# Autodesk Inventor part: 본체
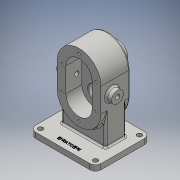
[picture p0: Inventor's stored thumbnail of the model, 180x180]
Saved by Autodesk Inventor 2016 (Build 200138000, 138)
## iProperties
Created: 2020-09
Part Number: 본체
Material: 일반
Document SubType Name: Modeling
Designer: Windows7
Density: 1 g/cm^3
Appearance: 기본값
Author: Windows7
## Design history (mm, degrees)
sketch "스케치1"
  geometry: L1 (60, -50)-(-60, -50); L2 (-60, -50)-(-60, 50); L3 (-60, 50)-(60, 50); L4 (60, 50)-(60, -50); L5 (60, -50)-(-60, 50); L6 (-60, -50)-(60, 50); 1 further point
  constraints: 12 end point, 2 midpoint, 2 parallel, 1 horizontal, 1 perpendicular
  dimensions: "d0" = 120 distance of L2.end L3.end; "d1" = 100 distance of L3.end L1.start
extrude "돌출1" new body sketch "스케치1" distance "d2" = 10; taper "d3" = 0 deg
sketch "스케치6"
  geometry: 1 further point
node "작업 평면3"
sketch "스케치7"
  geometry: L1 (120, 0)-(0, 0) reference; L2 (60, 0)-(60, -90); L3 (20, -68)-(100, -68); L4 (100, -68)-(100, -112); L5 (100, -112)-(20, -112); L6 (20, -112)-(20, -68); L7 (20, -68)-(100, -112); L8 (100, -68)-(20, -112); A1 r 40 centre (60, -112) between (20, -112) and (100, -112); A2 r 40 centre (60, -68) between (100, -68) and (20, -68)
  constraints: 14 end point, 4 point on circle, 2 centre point, 2 midpoint, 2 parallel, 1 horizontal, 1 perpendicular, 1 vertical
  dimensions: "d22" = 90 distance of L2.start L2.end; "d23" = 44 distance of L5.end L3.start; "d24" = 80 distance between parallel lines of L6 L4; "d25" = 40 radius of A1; "d26" = 40 radius of A2
extrude "돌출3" join sketch "스케치7" distance "d27" = 53; taper "d28" = 0 deg
sketch "스케치8"
  geometry: 1 further point
sketch "스케치9"
  geometry: L1 (20, 112)-(20, 68) reference; L2 (100, 68)-(100, 112) reference; L3 (36, 112)-(36, 68); L4 (84, 112)-(84, 68); L5 (60, 0)-(60, 171.433); A1 r 40 centre (60, 112) between (100, 112) and (20, 112) reference; A2 r 40 centre (60, 68) between (20, 68) and (100, 68) reference; A3 r 24 centre (60, 112) between (84, 112) and (36, 112); A4 r 24 centre (60, 68) between (36.002, 68.312) and (84, 68)
  constraints: 6 end point, 5 point on circle, 2 centre point, 2 vertical, 1 tangent, 1 other
  dimensions: "d29" = 24 radius of A3; "d30" = 24 radius of A4
extrude "돌출4" cut sketch "스케치9" distance "d31" = 29; taper "d32" = 0 deg
node "작업 평면4"
sketch "스케치10"
  geometry: L1 (0, 0)-(120, 0) reference; L2 (60, 0)-(60, -90); L3 (60, -90)-(60, -112); C1 r 19 at (60, -112)
  constraints: 4 end point, 1 centre point, 1 coincident, 1 point on line, 1 vertical
  dimensions: "d34" = 90 distance of L2.start L2.end; "d35" = 22 distance of L2.end L3.end; "d36" = 19 radius of C1
extrude "돌출5" join sketch "스케치10" stored distance "d37" = 29; taper "d38" = 0 deg
sketch "스케치11"
  geometry: C1 r 19 at (0, 0) reference; C2 r 14 at (0, 0); 1 further point
  constraints: 1 centre point, 1 coincident
  dimensions: "d39" = 14 radius of C2
extrude "돌출6" cut sketch "스케치11" distance "d40" = 7.3; taper "d41" = 0 deg
chamfer "모따기1" distance "d42" = 0.35; stored, may be unused: second distance "d43" = 2, angle "d44" = 60 deg
fillet "모깎기1" dims "d45" = 0.5
sketch "스케치14"
  geometry: L1 (36, 68)-(36, 112) reference; L2 (84, 112)-(84, 68) reference; L3 (60, 0)-(60, 112); L4 (0, 0)-(120, 0) reference; C1 r 19 at (60, 112) reference; C2 r 12.5 at (60, 112); A1 r 24 centre (60, 112) between (84, 112) and (36, 112) reference; A2 r 24 centre (60, 68) between (36, 68) and (84, 68) reference
  constraints: 2 end point, 1 centre point, 1 coincident, 1 perpendicular
  dimensions: "d48" = 112 distance of L3.start L3.end (derived); "d49" = 12.5 radius of C2
  node "투영된 루프2"
extrude "돌출7" cut sketch "스케치14" distance "d50" = 15; taper "d51" = 0 deg
sketch "스케치15"
  geometry: 1 further point
sketch "스케치16"
  geometry: C1 r 12.5 at (60, 112) reference; C2 r 8.5 at (60, 112); 1 further point
  constraints: 1 centre point, 1 coincident
  dimensions: "d52" = 8.5 radius of C2
extrude "돌출8" cut sketch "스케치16" stored distance "d53" = 15; taper "d54" = 0 deg
chamfer "모따기2" distance "d55" = 1; stored, may be unused: second distance "d56" = 2, angle "d57" = 30 deg
sketch "스케치18"
  geometry: 1 further point
sketch "스케치19"
  geometry: L1 (60, 112)-(60, 68); C1 r 8.5 at (60, 112) reference; C2 r 19 at (60, 112) reference; C3 r 12.5 at (60, 68); 1 further point
  constraints: 2 end point, 1 centre point, 1 coincident, 1 vertical
  dimensions: "d58" = 44 distance of L1.start L1.end; "d59" = 12.5 radius of C3
extrude "돌출9" cut sketch "스케치19" distance "d60" = 15; taper "d61" = 0 deg
chamfer "모따기3" distance "d62" = 1; stored, may be unused: second distance "d63" = 2, angle "d64" = 30 deg
sketch "스케치24"
  geometry: L1 (-40, -12)-(40, -12); L2 (40, -12)-(40, 25); L3 (40, 25)-(-40, 25); L4 (-40, 25)-(-40, -12); L5 (-60, 50)-(60, 50) reference; L6 (0, 0)-(0, 19.462)
  constraints: 10 end point, 2 parallel, 1 horizontal, 1 perpendicular, 1 vertical, 1 other
  dimensions: "d67" = 25 distance between parallel lines of L5 L3; "d68" = 37 distance between parallel lines of L3 L1; "d69" = 80 distance between parallel lines of L2 L4
extrude "돌출10" join sketch "스케치24" stored distance "d70" = 15; taper "d71" = 0 deg
sketch "스케치25"
  geometry: 1 further point
fillet "모깎기2" dims "d72" = 10
sketch "스케치26"
  geometry: L1 (-60, 40)-(-60, -40) reference; L2 (-50, -50)-(50, -50) reference; L3 (60, -40)-(60, 40) reference; L4 (50, 50)-(-50, 50) reference; L5 (-40, -12)-(-40, 25) reference; L6 (-40, 25)-(40, 25) reference; L7 (40, 25)-(40, -12) reference; L8 (40, -12)-(-40, -12) reference; A1 r 10 centre (-50, 40) between (-50, 50) and (-60, 40) reference; A2 r 10 centre (-50, -40) between (-60, -40) and (-50, -50) reference; A3 r 10 centre (50, -40) between (50, -50) and (60, -40) reference; A4 r 10 centre (50, 40) between (60, 40) and (50, 50) reference; 5 further points
  constraints: 4 coincident
hole "구멍1" sketch "스케치26" at (50, 40), (-50, 40), (-50, -40), (50, -40) diameter "d73" = 9; stored, may be unused: countersink angle "d77" = 90 deg, drill point angle "d79" = 118 deg; dims "d74" = 6, "d75" = 4, "d76" = 2, "d78" = 8
fillet "모깎기3" dims "d80" = 3
fillet "모깎기4" dims "d81" = 3
fillet "모깎기5" dims "d82" = 3
fillet "모깎기6" dims "d83" = 3
node "작업 평면5"
sketch "스케치28"
  geometry: L1 (-68, 20)-(22, 20); C1 r 11 at (22, 20)
  constraints: 2 end point, 1 centre point, 1 coincident, 1 horizontal
  dimensions: "d87" = 90 distance of L1.start L1.end; "d88" = 11 radius of C1
extrude "돌출11" join sketch "스케치28" distance "d89" = 10; taper "d90" = 0 deg
fillet "모깎기7" dims "d91" = 3
sketch "스케치29"
  geometry: C1 r 11 at (22, 20) reference; 1 further point
extrude "돌출12" join sketch "스케치29" distance "d92" = 10; taper "d93" = 0 deg
fillet "모깎기8" dims "d94" = 3
fillet "모깎기9" dims "d95" = 3
sketch "스케치30"
  geometry: C1 r 11 at (0, 0) reference; 2 further points
  constraints: 1 coincident
hole "구멍2" sketch "스케치30" at (0, 0) diameter "d96" = 8.376; stored, may be unused: countersink angle "d100" = 90 deg, drill point angle "d102" = 118 deg; dims "d97" = 20, "d98" = 4, "d99" = 2, "d101" = 27.3
sketch "스케치31"
  geometry: L1 (36, 68)-(36, 112) reference; L2 (84, 112)-(84, 68) reference; L3 (20, 112)-(20, 68) reference; L4 (100, 68)-(100, 112) reference; L5 (60, 112)-(60, 68); A1 r 24 centre (60, 112) between (84, 112) and (36, 112) reference; A2 r 24 centre (60, 68) between (36, 68) and (84, 68) reference; A3 r 40 centre (60, 112) between (100, 112) and (20, 112) reference; A4 r 40 centre (60, 68) between (20, 68) and (100, 68) reference; A5 r 31 centre (60, 112) between (90.942, 113.889) and (29.058, 113.889); A6 r 31 centre (60, 68) between (29, 67.835) and (91, 67.835); 3 further points
  constraints: 6 point on circle, 2 centre point, 2 end point, 1 vertical
  dimensions: "d103" = 31 radius of A5; "d111" = 31 radius of A6
hole "구멍3" sketch "스케치31" at (60, 143) diameter "d104" = 4.134; stored, may be unused: countersink angle "d108" = 90 deg, drill point angle "d110" = 118 deg; dims "d105" = 10, "d106" = 4, "d107" = 2, "d109" = 12
sketch "스케치32"
  geometry: L1 (36, 68)-(36, 112) reference; L2 (84, 112)-(84, 68) reference; L3 (20, 112)-(20, 68) reference; L4 (100, 68)-(100, 112) reference; L5 (29, 111.816)-(29, 68); L6 (91, 68)-(90.943, 113.888); L7 (20, 90)-(100, 90); L8 (20, 68)-(20, 112) reference; L9 (20, 68)-(100, 68); L10 (20, 112)-(100, 112); C1 r 2.067 at (60, 143) reference; A1 r 24 centre (60, 112) between (84, 112) and (36, 112) reference; A2 r 24 centre (60, 68) between (36, 68) and (84, 68) reference; A3 r 40 centre (60, 112) between (100, 112) and (20, 112) reference; A4 r 40 centre (60, 68) between (20, 68) and (100, 68) reference; A5 r 31.001 centre (60, 112) between (90.943, 113.888) and (29, 111.816); A6 r 31 centre (60, 68) between (29, 68) and (91, 68); 6 further points
  constraints: 10 end point, 5 point on circle, 4 coincident, 2 centre point, 2 midpoint, 1 horizontal, 1 perpendicular
  dimensions: "d113" = 31 radius of A6
hole "구멍4" sketch "스케치32" at (91, 68), (60, 37), (29, 68), (29, 111.816), (90.943, 113.888) diameter "d114" = 4.134; stored, may be unused: countersink angle "d118" = 90 deg, drill point angle "d120" = 118 deg; dims "d115" = 10, "d116" = 4, "d117" = 2, "d119" = 12
node "작업 평면6"
sketch "스케치33"
  geometry: L1 (-60, 40)-(-60, -40) reference; L2 (-50, -50)-(50, -50) reference; L3 (60, -40)-(60, 40) reference; L4 (50, 50)-(-50, 50) reference; L5 (-43, 22)-(-43, -9) reference; L6 (37, 28)-(-37, 28) reference; L7 (43, -9)-(43, 22) reference; L8 (-37, -15)-(37, -15) reference; L9 (-60, -38)-(0, -38); L10 (0, -38)-(0, -50); L11 (-20.739, -34.998)-(20.739, -34.998); L12 (20.739, -34.998)-(20.739, -41.002); L13 (20.739, -41.002)-(-20.739, -41.002); L14 (-20.739, -41.002)-(-20.739, -34.998); L15 (-20.739, -34.998)-(20.739, -41.002); C1 r 4.5 at (50, -40) reference; C2 r 4.5 at (-50, 40) reference; C3 r 4.5 at (50, 40) reference; C4 r 4.5 at (-50, -40) reference; A1 r 10 centre (-50, 40) between (-50, 50) and (-60, 40) reference; A2 r 10 centre (-50, -40) between (-60, -40) and (-50, -50) reference; A3 r 10 centre (50, -40) between (50, -50) and (60, -40) reference; A4 r 10 centre (50, 40) between (60, 40) and (50, 50) reference; A5 r 6 centre (-37, -9) between (-43, -9) and (-37, -15) reference; A6 r 6 centre (-37, 22) between (-37, 28) and (-43, 22) reference; A7 r 6 centre (37, 22) between (43, 22) and (37, 28) reference; A8 r 6 centre (37, -9) between (37, -15) and (43, -9) reference; 2 further points
  constraints: 6 end point, 2 midpoint, 1 coincident, 1 horizontal, 1 perpendicular, 1 point on line, 2 other
  dimensions: "d122" = 12 distance between parallel lines of L2 L9; "d123" = 60 distance between parallel lines of L1 L10
feature "엠보싱1" sketch "스케치33" dims "d22" = 90, "d23" = 44, "d24" = 80, "d25" = 40, "d26" = 40, "d124" = 0.5, "d125" = 0
node "솔리드1"
node "투영된 루프1"
node "투영된 루프3"
node "투영된 루프4"
node "투영된 루프5"
node "투영된 루프6"
node "투영된 루프7"
node "투영된 루프8"
other parameters: "d21" = -17, "d33" = 17, "d121" = 36.75
